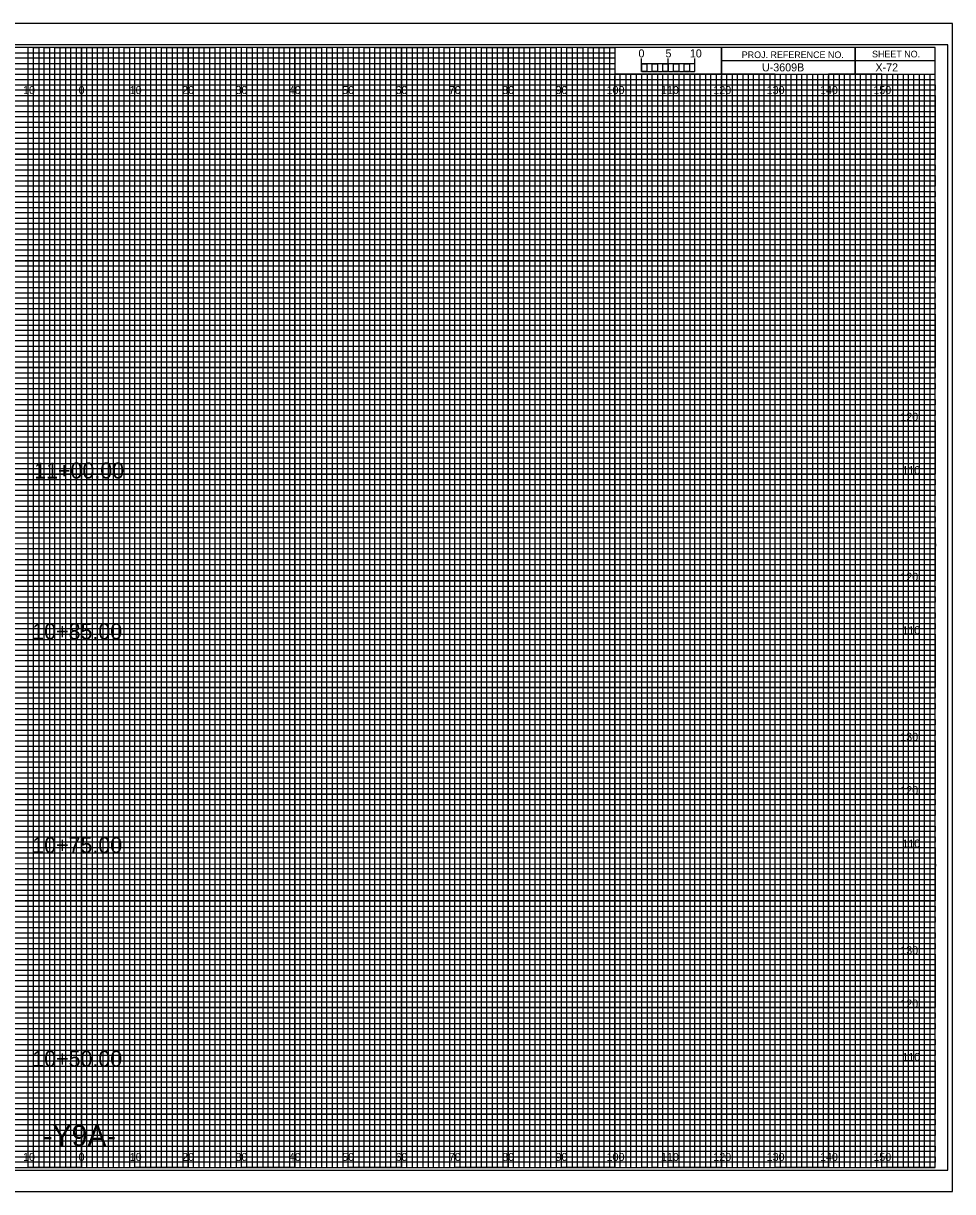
# Model space of a CAD drawing. Extents: x -13 to 323, y -5 to 215.
# Drawn here: x 149.1 to 323.3, y -4.5 to 214.5 of the extents above; entities that cross this region are included whole.
import ezdxf

# ---------------------------------------------------------------- set-up
doc = ezdxf.new("R2010")
doc.units = 0
for name, color, linetype in [('Prop XS Alignment Label', 7, 'Continuous'), ('Prop XS Bar Scale Labels', 7, 'Continuous'), ('Prop XS Elevation Labels', 7, 'Continuous'), ('Prop XS Offset Labels', 7, 'Continuous'), ('Prop XS Project Number', 7, 'Continuous'), ('Prop XS Sheet Number', 7, 'Continuous'), ('Prop XS Station Labels', 7, 'Continuous'), ('Sheet Cross Section CELL', 7, 'Continuous'), ('Sheet Cross Section Grid Major CELL', 7, 'Continuous'), ('Sheet Cross Section Grid Middle CELL', 7, 'Continuous'), ('Sheet Cross Section Grid Minor 1 CELL', 7, 'Continuous'), ('Sheet Cross Section Grid Minor 2 CELL', 7, 'Continuous'), ('Sheet Cross Section Scale CELL', 7, 'Continuous'), ('Sheet Cutting Line CELL', 7, 'Continuous'), ('Sheet DOT Grid CELL', 7, 'Continuous'), ('Sheet Plot Border Inside CELL', 7, 'Continuous'), ('Sheet Plot Border Outside CELL', 7, 'Continuous')]:
    doc.layers.add(name, color=color, linetype=linetype)

msp = doc.modelspace()

# ---------------------------------------------------------------- linework, layer by layer
at = {"layer": 'Sheet Cross Section CELL'}
for p, q in [((305, 210), (305, 205)), ((305, 205), (305, 210)), ((280, 207.5), (280, 205)), ((320, 207.49), (280, 207.49)), ((280, 205), (320, 205))]:
    msp.add_line(p, q, dxfattribs=at)
for points in [[(320, 210), (0, 210), (0, 0), (320, 0)], [(280, 210), (260, 210), (260, 205.03), (280, 205.03)], [(320, 210), (280, 210), (280, 205), (320, 205)]]:
    msp.add_lwpolyline(points, close=True, dxfattribs=at)
at = {"layer": 'Sheet Cross Section Grid Major CELL'}
for p, q in [((150, 210), (140, 210)), ((150, 0), (150, 210)), ((170, 210), (160, 210)), ((160, 210), (160, 0)), ((170, 0), (170, 210)), ((190, 210), (180, 210)), ((180, 210), (180, 0)), ((190, 0), (190, 210)), ((210, 210), (200, 210)), ((200, 210), (200, 0)), ((210, 0), (210, 210)), ((230, 210), (220, 210)), ((220, 210), (220, 0)), ((230, 0), (230, 210)), ((250, 210), (240, 210)), ((240, 210), (240, 0)), ((250, 0), (250, 210)), ((260, 210), (260, 0)), ((270, 0), (270, 205)), ((290, 205), (280, 205)), ((280, 205), (280, 0)), ((290, 0), (290, 205)), ((310, 205), (300, 205)), ((300, 205), (300, 0)), ((310, 0), (310, 205)), ((160, 0), (150, 0)), ((180, 0), (170, 0)), ((200, 0), (190, 0)), ((220, 0), (210, 0)), ((240, 0), (230, 0)), ((260, 0), (250, 0)), ((280, 0), (270, 0)), ((300, 0), (290, 0)), ((320, 0), (310, 0)), ((320, 0), (320, 0))]:
    msp.add_line(p, q, dxfattribs=at)
for points in [[(0, 200), (320, 200), (320, 190), (0, 190)], [(0, 180), (320, 180), (320, 170), (0, 170)], [(0, 160), (320, 160), (320, 150), (0, 150)], [(0, 140), (320, 140), (320, 130), (0, 130)], [(0, 120), (320, 120), (320, 110), (0, 110)], [(0, 100), (320, 100), (320, 90), (0, 90)], [(0, 80), (320, 80), (320, 70), (0, 70)], [(0, 60), (320, 60), (320, 50), (0, 50)], [(0, 40), (320, 40), (320, 30), (0, 30)], [(0, 20), (320, 20), (320, 10), (0, 10)]]:
    msp.add_lwpolyline(points, dxfattribs=at)
at = {"layer": 'Sheet Cross Section Grid Middle CELL'}
for points in [[(145, 0), (155, 0), (155, 210), (165, 210), (165, 0), (175, 0), (175, 210), (185, 210), (185, 0), (195, 0), (195, 210), (205, 210), (205, 0), (215, 0), (215, 210), (225, 210), (225, 0), (235, 0), (235, 210), (245, 210), (245, 0), (255, 0), (255, 210), (259.93, 210), (260, 210), (260, 205), (264.99, 205), (264.99, 0), (275, 0), (275, 205), (285, 205), (285, 0), (295, 0), (295, 205), (305, 205), (305, 0), (315, 0), (315, 205)], [(0, 205), (275, 205)], [(0, 185), (320, 185), (320, 195), (0, 195)], [(0, 165), (320, 165), (320, 175), (0, 175)], [(0, 145), (320, 145), (320, 155), (0, 155)], [(0, 125), (320, 125), (320, 135), (0, 135)], [(0, 105), (320, 105), (320, 115), (0, 115)], [(0, 85), (320, 85), (320, 95), (0, 95)], [(0, 65), (320, 65), (320, 75), (0, 75)], [(0, 45), (320, 45), (320, 55), (0, 55)], [(0, 25), (320, 25), (320, 35), (0, 35)], [(0, 5), (320, 5), (320, 15), (0, 15)]]:
    msp.add_lwpolyline(points, dxfattribs=at)
at = {"layer": 'Sheet Cross Section Grid Minor 1 CELL'}
for p, q in [((0, 209), (260, 209)), ((260, 209), (260, 207.98)), ((260, 207.98), (0, 207.98)), ((0, 207), (260, 207)), ((260, 205.89), (0, 205.89)), ((260, 207), (260, 205.89)), ((0, 204), (320, 204))]:
    msp.add_line(p, q, dxfattribs=at)
for points in [[(0, 203), (270, 203), (320, 203), (320, 202), (0, 202)], [(0, 201), (320, 201), (320, 199), (0, 199)], [(0, 198), (320, 198), (320, 197), (0, 196.98)], [(0, 196), (320, 196), (320, 194), (0, 194)], [(0, 193), (320, 193), (320, 192), (0, 192)], [(0, 191), (320, 191), (320, 189), (0, 189)], [(0, 188), (320, 188), (320, 187), (0, 187)], [(0, 186), (320, 186), (320, 184), (0, 184)], [(0, 183), (320, 183), (320, 182), (0, 182)], [(0, 181), (320, 181), (320, 179), (0, 179)], [(0, 178), (320, 178), (320, 177), (0, 177)], [(0, 176), (320, 176), (320, 173.95), (320, 173), (320, 172), (0, 172)], [(0, 174), (320, 174), (320, 173), (0, 173)], [(0, 171), (320, 171), (320, 169), (0, 169.03)], [(0, 169.03), (320, 169), (320, 168), (0, 168)], [(0, 167), (320, 167), (320, 166), (0, 166)], [(0, 164), (320, 164), (320, 163), (0, 163)], [(0, 162), (320, 162), (320, 161), (0, 161)], [(-0.07, 158.89), (320, 158.89), (320, 157.88), (-0.07, 157.88)], [(0, 157), (320, 157), (320, 156), (0, 156)], [(0, 154), (320, 154), (320, 153), (0, 153)], [(0, 152), (320, 152), (320, 151), (0, 151)], [(0, 149), (320, 149), (320, 148), (0, 148)], [(0, 147), (320, 147), (320, 146), (0, 146)], [(0, 144), (320, 144), (320, 143), (0, 143)], [(0, 142), (320, 142), (320, 141), (0, 141)], [(0, 139), (320, 139), (319.99, 137.98), (0, 138)], [(0, 137), (320, 137), (320, 136), (0, 136)], [(0, 134), (320, 134), (320, 133), (0, 133)], [(0, 132), (320, 132), (320, 131), (0, 131)], [(0, 129), (320, 129), (320, 128), (0, 128)], [(0, 127), (320, 127), (320, 126), (0, 126)], [(0, 124), (320, 124), (320, 123), (0, 123)], [(0, 122), (320, 122), (320, 121), (0, 121)], [(0, 119), (320, 119), (320, 118), (0, 118)], [(0, 116.99), (320.07, 116.91), (320, 116), (0, 116)], [(0, 114), (320, 114), (320, 113), (0, 113)], [(0, 112), (320, 112), (320, 111), (0, 111)], [(0, 109), (320, 109), (320, 108), (0, 108)], [(0, 107), (320, 107), (320, 106), (0, 106)], [(0, 104), (320, 104), (320, 103), (0, 103)], [(0, 102), (320, 102), (320, 101), (0, 101)], [(0, 99), (320, 99), (320, 98), (0, 98)], [(0, 97), (320, 97), (320, 96), (0, 96)], [(0, 94), (320, 94), (320, 93), (0, 93)], [(0, 92), (320, 92), (320, 91), (0, 91)], [(0, 89), (320, 89), (320, 88), (0, 88)], [(0, 87), (320, 87), (320, 86), (0, 86)], [(0, 84), (320, 84), (320, 83), (0, 83)], [(0, 82), (320, 82), (320, 81), (0, 81)], [(0, 79), (320, 79), (319.99, 77.98), (0, 78)], [(0, 77), (320, 77), (320, 76), (0, 76)], [(0, 74), (320, 74), (320, 73), (0, 73)], [(0, 72), (320, 72), (320, 71), (0, 71)], [(0, 69), (320, 69), (320, 68), (0, 68)], [(0, 67), (320, 67), (320, 66), (0, 66)], [(0, 64), (320, 64), (320, 63), (0, 63)], [(0, 62), (320, 62), (320, 61), (0, 61)], [(0, 59), (320, 59), (320, 58), (0, 58)], [(0, 56.99), (320.07, 56.91), (320, 56), (0, 56)], [(0, 54), (320, 54), (320, 53), (0, 53)], [(0, 52), (320, 52), (320, 51), (0, 51)], [(0, 49), (320, 49), (320, 48), (0, 48)], [(0, 47), (320, 47), (320, 46), (0, 46)], [(0, 44), (320, 44), (320, 43), (0, 43)], [(0, 42), (320, 42), (320, 41), (0, 41)], [(0, 39), (320, 39), (320, 38), (0, 38)], [(0, 37), (320, 37), (320, 36), (0, 36)], [(0, 34), (320, 34), (320, 33), (0, 33)], [(0, 32), (320, 32), (320, 31), (0, 31)], [(0, 29), (320, 29), (320, 28), (0, 28)], [(0, 27), (320, 27), (320, 26), (0, 26)], [(0, 24), (320, 24), (320, 23), (0, 23)], [(0, 22), (320, 22), (320, 21), (0, 21)], [(0, 19), (320, 19), (320, 18), (0, 18)], [(0, 17), (320, 17), (320, 16), (0, 16)], [(0, 14), (320, 14), (320, 13), (0, 13)], [(0, 12), (320, 12), (320, 11), (0, 11)], [(0, 9), (320, 9), (320, 8), (0, 8)], [(0, 7), (320, 7), (320, 6), (0, 6)], [(0, 4), (320, 4), (320, 3), (0, 3)], [(0, 2), (320, 2), (320, 1), (0, 1)]]:
    msp.add_lwpolyline(points, dxfattribs=at)
at = {"layer": 'Sheet Cross Section Grid Minor 2 CELL'}
for p, q in [((267, 205), (266.01, 205)), ((266.01, 205), (266.01, 0)), ((267, 0), (267, 205)), ((269, 205), (268, 205)), ((268, 205), (268, 0)), ((269, 0), (269, 205)), ((266.01, 0), (265, 0)), ((268, 0), (267, 0))]:
    msp.add_line(p, q, dxfattribs=at)
for points in [[(150, 0), (151, 0), (151, 210), (152, 210), (152, 0)], [(152, 0), (153, 0), (153, 210), (154, 210), (154, 0)], [(155, 0), (156, 0), (156, 210), (157, 210), (157, 0)], [(157, 0), (158, 0), (158, 210), (159, 210), (159, 0)], [(160, 0), (161, 0), (161, 210), (162, 210), (162, 0)], [(162, 0), (163, 0), (163, 210), (164, 210), (164, 0)], [(165, 0), (166, 0), (166, 210), (167, 210), (167, 0)], [(167, 0), (168, 0), (168, 210), (169, 210), (169, 0)], [(170, 0), (171, 0), (171, 210), (172, 210), (172, 0)], [(172, 0), (173, 0), (173, 210), (174, 210), (174, 0)], [(175, 0), (176, 0), (176, 210), (177, 210), (177, 0)], [(177, 0), (178, 0), (178, 210), (179, 210), (179, 0)], [(180, 0), (181, 0), (181, 210), (182, 210), (182, 0)], [(182, 0), (183, 0), (183, 210), (184, 210), (184, 0)], [(185, 0), (186, 0), (186, 210), (187, 210), (187, 0)], [(187, 0), (188, 0), (188, 210), (189, 210), (189, 0)], [(190, 0), (191, 0), (191, 210), (192, 210), (192, 0)], [(192, 0), (193, 0), (193, 210), (194, 210), (194, 0)], [(195, 0), (196, 0), (196, 210), (197, 210), (197, 0)], [(197, 0), (198, 0), (198, 210), (199, 210), (199, 0)], [(200, 0), (201, 0), (201, 210), (202, 210), (202, 0)], [(202, 0), (203, 0), (203, 210), (204, 210), (204, 0)], [(205, 0), (206, 0), (206, 210), (207, 210), (207, 0)], [(207, 0), (208, 0), (208, 210), (209, 210), (209, 0)], [(210, 0), (211, 0), (211, 210), (212, 210), (212, 0)], [(212, 0), (213, 0), (213, 210), (214, 210), (214, 0)], [(215, 0), (216, 0), (216, 210), (217, 210), (217, 0)], [(217, 0), (218, 0), (218, 210), (219, 210), (219, 0)], [(220, 0), (221, 0), (221, 210), (222, 210), (222, 0)], [(222, 0), (223, 0), (223, 210), (224, 210), (224, 0)], [(225, 0), (226, 0), (226, 210), (227, 210), (227, 0)], [(227, 0), (228, 0), (228, 210), (229, 210), (229, 0)], [(230, 0), (231, 0), (231, 210), (232, 210), (232, 0)], [(232, 0), (233, 0), (233, 210), (234, 210), (234, 0)], [(235, 0), (236, 0), (236, 210), (237, 210), (237, 0)], [(237, 0), (238, 0), (238, 210), (239, 210), (239, 0)], [(240, 0), (241, 0), (241, 210), (242, 210), (242, 0)], [(242, 0), (243, 0), (243, 210), (244, 210), (244, 0)], [(245, 0), (246, 0), (246, 210), (247, 210), (247, 0)], [(247, 0), (248, 0), (248, 210), (249, 210), (249, 0)], [(250, 0), (251, 0), (251, 210), (252, 210), (252, 0)], [(252, 0), (253, 0), (253, 210), (254, 210), (254, 0)], [(255, 0), (256, 0), (256, 210), (257, 210), (257, 0)], [(257, 0), (258, 0), (258, 210), (259, 210), (259, 0)], [(260, 0), (261, 0), (261, 205), (262.02, 205), (262.02, 0)], [(262, 0), (263, 0), (263, 205), (263.99, 205), (263.99, 0)], [(270, 0), (270.98, 0), (270.98, 205), (272, 205), (272, 0)], [(272, 0), (273, 0), (273, 205), (274.05, 205), (274.05, 0)], [(275, 0), (276, 0), (276, 205), (277, 205), (277, 0)], [(277, 0), (278, 0), (278, 205), (279, 205), (279, 0)], [(280, 0), (281, 0), (281, 205), (282, 205), (282, 0)], [(282, 0), (283, 0), (283, 205), (284, 205), (284, 0)], [(285, 0), (286, 0), (286, 205), (287, 205), (287, 0)], [(287, 0), (288, 0), (288, 205), (289, 205), (289, 0)], [(290, 0), (291, 0), (291, 205), (292, 205), (292, 0)], [(292, 0), (293, 0), (293, 205), (294, 205), (294, 0)], [(295, 0), (296, 0), (296, 205), (297, 205), (297, 0)], [(297, 0), (298, 0), (298, 205), (299, 205), (299, 0)], [(300, 0), (301, 0), (301, 205), (302, 205), (302, 0)], [(302, 0), (303, 0), (303, 205), (304, 205), (304, 0)], [(305, 0), (306, 0), (306, 205), (307, 205), (307, 0)], [(307, 0), (308, 0), (308, 205), (309, 205), (309, 0)], [(310, 0), (311, 0), (311, 205), (312, 205), (312, 0)], [(312, 0), (313, 0), (313, 205), (314, 205), (314, 0)], [(315, 0), (316, 0), (316, 205), (317, 205), (317, 0)], [(317, 0), (318, 0), (318, 205), (319, 205), (319, 0)]]:
    msp.add_lwpolyline(points, dxfattribs=at)
at = {"layer": 'Sheet Cross Section Scale CELL'}
for p, q in [((265, 205.49), (265, 207.9)), ((265, 206.9), (265, 207.9)), ((270, 205.49), (270, 207.9)), ((275, 205.49), (275, 207.9)), ((275, 206.9), (275, 207.9))]:
    msp.add_line(p, q, dxfattribs=at)
for points in [[(275, 206.9), (265, 206.9), (265, 205.49), (275, 205.49)], [(265, 206.9), (266, 206.9), (266, 205.49), (265, 205.49)], [(267, 206.9), (268, 206.9), (268, 205.49), (267, 205.49)], [(269, 206.9), (270, 206.9), (270, 205.49), (269, 205.49)], [(271, 206.9), (272, 206.9), (272, 205.49), (271, 205.49)], [(273, 206.9), (274, 206.9), (274, 205.49), (273, 205.49)]]:
    msp.add_lwpolyline(points, close=True, dxfattribs=at)
at = {"layer": 'Sheet Cutting Line CELL'}
for p, q in [((323.3, 214.5), (-13.4, 214.5)), ((-13.4, -4.5), (323.3, -4.5))]:
    msp.add_line(p, q, dxfattribs=at)
at = {"layer": 'Sheet DOT Grid CELL'}
for p, q in [((150, 0), (150, 210)), ((160, 0), (160, 210)), ((170, 0), (170, 210)), ((180, 0), (180, 210)), ((190, 0), (190, 210)), ((200, 0), (200, 210)), ((210, 0), (210, 210)), ((220, 0), (220, 210)), ((230, 0), (230, 210)), ((240, 0), (240, 210)), ((250, 0), (250, 210)), ((260, 0), (260, 204.69)), ((270, 0), (270, 204.69)), ((280, 0), (280, 204.69)), ((290, 0), (290, 204.69)), ((300, 0), (300, 204.69)), ((310, 0), (310, 204.69)), ((0, 200), (320, 200)), ((0, 190), (320, 190)), ((0, 180), (320, 180)), ((0, 170), (320, 170)), ((0, 160), (320, 160)), ((0, 150), (320, 150)), ((0, 140), (320, 140)), ((0, 130), (320, 130)), ((0, 120), (320, 120)), ((0, 110), (320, 110)), ((0, 100), (320, 100)), ((0, 90), (320, 90)), ((0, 80), (320, 80)), ((0, 70), (320, 70)), ((0, 60), (320, 60)), ((0, 50), (320, 50)), ((0, 40), (320, 40)), ((0, 30), (320, 30)), ((0, 20), (320, 20)), ((0, 10), (320, 10))]:
    msp.add_line(p, q, dxfattribs=at)
at = {"layer": 'Sheet Plot Border Inside CELL'}
msp.add_lwpolyline([(-10.8, -0.5), (322.4, -0.5), (322.4, 210.5), (-10.8, 210.5)], close=True, dxfattribs=at)
at = {"layer": 'Sheet Plot Border Outside CELL'}
msp.add_lwpolyline([(-13.4, -4.5), (323.3, -4.5), (323.3, 214.5), (-13.4, 214.5)], close=True, dxfattribs=at)

# ---------------------------------------------------------------- texts
at = {"layer": 'Prop XS Alignment Label'}
msp.add_text('-Y9A-', height=4, dxfattribs=at).set_placement((152.78, 4))
at = {"layer": 'Prop XS Bar Scale Labels'}
for s, p in [('5', (269.47, 208.12)), ('10', (274.04, 208.12))]:
    msp.add_text(s, height=1.5, dxfattribs=at).set_placement(p)
at = {"layer": 'Prop XS Elevation Labels'}
for s, p in [('120', (313.5, 140)), ('110', (313.88, 130)), ('120', (313.5, 110)), ('110', (313.88, 100)), ('130', (313.49, 80)), ('120', (313.5, 70)), ('110', (313.88, 60)), ('130', (313.49, 40)), ('120', (313.5, 30)), ('110', (313.88, 20))]:
    msp.add_text(s, height=1.5, dxfattribs=at).set_placement(p)
at = {"layer": 'Prop XS Offset Labels'}
for s, p in [('10', (149.04, 201.25)), ('0', (159.45, 201.25)), ('0', (159.45, 201.25)), ('10', (169.04, 201.25)), ('20', (178.86, 201.25)), ('30', (188.86, 201.25)), ('40', (198.86, 201.25)), ('50', (208.86, 201.25)), ('60', (218.86, 201.25)), ('70', (228.86, 201.25)), ('80', (238.86, 201.25)), ('90', (248.86, 201.25)), ('100', (258.44, 201.25)), ('110', (268.62, 201.25)), ('120', (278.44, 201.25)), ('130', (288.44, 201.25)), ('140', (298.44, 201.25)), ('150', (308.44, 201.25)), ('10', (149.04, 1.25)), ('0', (159.45, 1.25)), ('0', (159.45, 1.25)), ('10', (169.04, 1.25)), ('20', (178.86, 1.25)), ('30', (188.86, 1.25)), ('40', (198.86, 1.25)), ('50', (208.86, 1.25)), ('60', (218.86, 1.25)), ('70', (228.86, 1.25)), ('80', (238.86, 1.25)), ('90', (248.86, 1.25)), ('100', (258.44, 1.25)), ('110', (268.62, 1.25)), ('120', (278.44, 1.25)), ('130', (288.44, 1.25)), ('140', (298.44, 1.25)), ('150', (308.44, 1.25))]:
    msp.add_text(s, height=1.5, dxfattribs=at).set_placement(p)
at = {"layer": 'Prop XS Project Number'}
msp.add_text('U-3609B', height=1.5, dxfattribs=at).set_placement((287.56, 205.5))
at = {"layer": 'Prop XS Sheet Number'}
msp.add_text('X-72', height=1.5, dxfattribs=at).set_placement((308.83, 205.5))
at = {"layer": 'Prop XS Station Labels'}
for s, p in [('11+00.00', (151.13, 129.18)), ('10+85.00', (150.77, 99.03)), ('10+75.00', (150.77, 58.97)), ('10+50.00', (150.77, 18.92))]:
    msp.add_text(s, height=3, dxfattribs=at).set_placement(p)
at = {"layer": 'Sheet Cross Section CELL'}
for s, p in [('PROJ. REFERENCE NO.', (283.77, 207.99)), ('SHEET NO.', (308.19, 208.12))]:
    msp.add_text(s, height=1.25, dxfattribs=at).set_placement(p)
at = {"layer": 'Sheet Cross Section Scale CELL'}
msp.add_text('0', height=1.5, dxfattribs=at).set_placement((264.41, 208.12))

doc.saveas('drawing.dxf')
